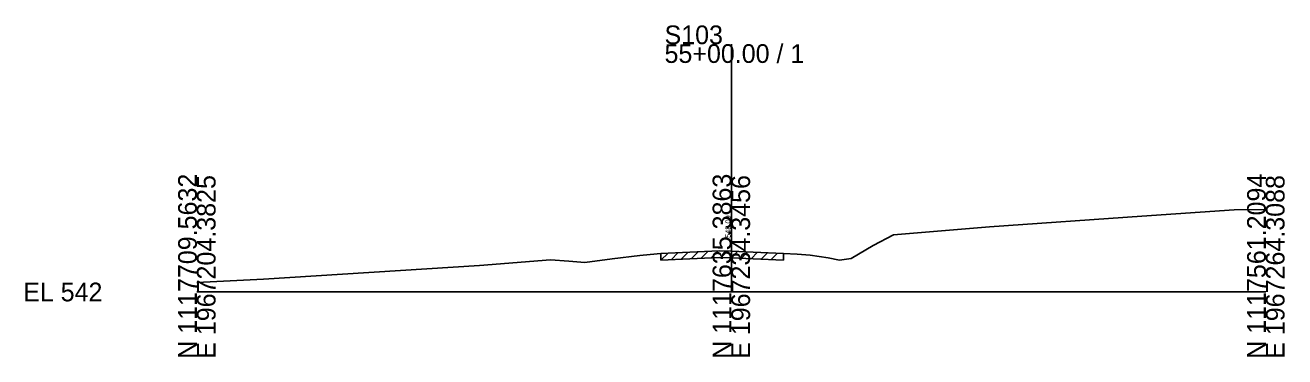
# Model space of a CAD drawing. Extents: x -26 to 163, y -10 to 45020.
# Drawn here: x -25.7 to 162.8, y 14990.3 to 15039.9 of the extents above; entities that cross this region are included whole.
import ezdxf

# ---------------------------------------------------------------- set-up
doc = ezdxf.new("R2010")
doc.units = 0
for name, color, linetype in [('RD_GPK_XS_Cell', 7, 'Continuous'), ('RD_XS_ExGround', 7, 'Continuous'), ('RD_XS_ExPaveRet', 7, 'Continuous'), ('RD_XS_TX_Elev_EX', 7, 'Continuous')]:
    doc.layers.add(name, color=color, linetype=linetype)

msp = doc.modelspace()

# ---------------------------------------------------------------- linework, layer by layer
at = {"layer": 'RD_GPK_XS_Cell'}
for p, q in [((80, 15000), (80, 15037.06)), ((0, 15000), (80, 15000)), ((80, 15000), (160, 15000))]:
    msp.add_line(p, q, dxfattribs=at)
at = {"layer": 'RD_XS_ExGround'}
for p, q in [((118.66, 15009.75), (141.43, 15011.33)), ((141.43, 15011.33), (155.24, 15012.31)), ((155.24, 15012.31), (160, 15012.35)), ((104.29, 15008.55), (118.66, 15009.75)), ((101.23, 15006.94), (104.29, 15008.55)), ((62.15, 15004.96), (66.31, 15005.46)), ((66.31, 15005.46), (67.84, 15005.61)), ((67.84, 15005.61), (69.47, 15005.76)), ((69.47, 15005.76), (73.8, 15005.96)), ((73.8, 15005.96), (78.18, 15006.17)), ((78.18, 15006.17), (80, 15006.09)), ((80, 15006.09), (83.27, 15005.96)), ((83.27, 15005.96), (87.83, 15005.77)), ((87.83, 15005.77), (89.84, 15005.65)), ((89.84, 15005.65), (91.8, 15005.5)), ((91.8, 15005.5), (94.47, 15005.11)), ((97.94, 15005.03), (101.23, 15006.94)), ((9.98, 15001.94), (42.33, 15003.98)), ((42.33, 15003.98), (52.93, 15004.81)), ((52.93, 15004.81), (55.66, 15004.6)), ((55.66, 15004.6), (58.05, 15004.42)), ((58.05, 15004.42), (62.15, 15004.96)), ((94.47, 15005.11), (96.19, 15004.78)), ((96.19, 15004.78), (97.24, 15004.93)), ((97.24, 15004.93), (97.94, 15005.03)), ((0, 15001.43), (9.98, 15001.94))]:
    msp.add_line(p, q, dxfattribs=at)
at = {"layer": 'RD_XS_ExPaveRet'}
for p, q in [((69.47, 15004.76), (70.52, 15005.81)), ((69.47, 15004.76), (69.47, 15005.76)), ((70.97, 15004.83), (72.02, 15005.88)), ((72.47, 15004.9), (73.52, 15005.95)), ((73.97, 15004.97), (75.02, 15006.02)), ((75.47, 15005.04), (76.52, 15006.09)), ((76.97, 15005.11), (78.02, 15006.16)), ((78.47, 15005.16), (79.43, 15006.12)), ((79.97, 15005.09), (80.93, 15006.06)), ((81.47, 15005.03), (82.43, 15005.99)), ((82.97, 15004.97), (83.93, 15005.93)), ((84.47, 15004.91), (85.43, 15005.87)), ((85.97, 15004.85), (86.93, 15005.81)), ((87.83, 15005.77), (87.83, 15004.77)), ((69.47, 15004.76), (73.8, 15004.96)), ((73.8, 15004.96), (78.18, 15005.17)), ((78.18, 15005.17), (80, 15005.09)), ((80, 15005.09), (83.27, 15004.96)), ((83.27, 15004.96), (87.83, 15004.77))]:
    msp.add_line(p, q, dxfattribs=at)

# ---------------------------------------------------------------- texts
at = {"layer": 'RD_GPK_XS_Cell'}
for s, p in [('S103', (70, 15037.06)), ('55+00.00 / 1', (70, 15034.26)), ('EL 542', (-26, 14998.6))]:
    msp.add_text(s, height=2.8, dxfattribs=at).set_placement(p)
for s, p in [('N 1117709.5632', (0, 14990)), ('E 1967204.3825', (2.8, 14990)), ('N 1117635.3863', (80, 14990)), ('E 1967234.3456', (82.8, 14990)), ('N 1117561.2094', (160, 14990)), ('E 1967264.3088', (162.8, 14990))]:
    msp.add_text(s, height=2.8, rotation=90, dxfattribs=at).set_placement(p)
at = {"layer": 'RD_XS_TX_Elev_EX'}
msp.add_text('548.09', height=0.8, rotation=90, dxfattribs=at).set_placement((79.9, 15008.09))

doc.saveas('drawing.dxf')
